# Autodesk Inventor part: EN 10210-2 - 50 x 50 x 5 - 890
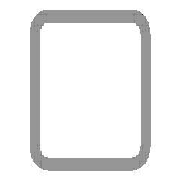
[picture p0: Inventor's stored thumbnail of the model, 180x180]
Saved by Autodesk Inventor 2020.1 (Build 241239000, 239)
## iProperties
_CCFamilyMember: 16
_CCFamilyDisplayName: DIN EN 10210-2 (USAS B17.1 quadratisch) - Rohrleitung — In Klammern angegebene Größen wurden aufgehoben
_FrameMemberDoc: Frame Member File
_Version: 15.0.0
_GetPNFromCC: 1
IsCustomPart: 1
Created: 2019-10
Part Number: EN 10210-2 - 50 x 50 x 5 - 890
Material: Stahl, weich
Description: Rohrleitung
Document SubType Name: Modeling
Standard: DIN
Designer: lutzd
Standard Revision: 2006-07
Standards Organization: DIN
Language: de-DE
Size Designation: 50 x 50 x 5
Categories: <MemberInstance><Categories><Category DisplayName="Profile" InternalName="089c4875-fa83-4c05-b084-43b9cc11f5ed" Mnemonic="GRDR"><CategoryParameter DisplayName="
Stock Number: 50 x 50 x 5
Mass: 6096.35 g
Surface Area: 3031.52 cm^2
Volume: 776.605 cm^3
Density: 7.85 g/cm^3
Appearance: Halbpoliert
G_L: 890,000 mm
G_W: 50,000 mm
G_H: 50,000 mm
Dimensions: 50x50x890 mm
Mass: 6,096 kg
DocNumber: ADSK-014096
Folder: .
+62D9DE20-FE77-4E76-B15A-D3B66BCC2A71+SCHNITTDETAIL1: Schnittwinkel 90,00 grd
+BCCFB225-26FE-409D-8E77-CCDF25C108BC+SCHNITTDETAIL2: Schnittwinkel 90,00 grd
Title: Profil-Bauteil
Author: lutzd
Revision Number: -
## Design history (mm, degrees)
node "Startebene"
node "Endebene"
sketch "Skizze"
  geometry: L1 (-25, -17.5)-(-25, 17.5); L2 (-17.5, 25)-(17.5, 25); L3 (25, 17.5)-(25, -17.5); L4 (17.5, -25)-(-17.5, -25); L5 (-15, 20)-(15, 20); L6 (20, 15)-(20, -15); L7 (15, -20)-(-15, -20); L8 (-20, -15)-(-20, 15); L9 (0, 37.175)-(0, -37.175) reference; L10 (-37.175, 0)-(37.175, 0) reference; A1 r 7.5 centre (-17.5, -17.5) between (-25, -17.5) and (-17.5, -25); A2 r 7.5 centre (-17.5, 17.5) between (-17.5, 25) and (-25, 17.5); A3 r 7.5 centre (17.5, 17.5) between (25, 17.5) and (17.5, 25); A4 r 7.5 centre (17.5, -17.5) between (17.5, -25) and (25, -17.5); A5 r 5 centre (-15, -15) between (-20, -15) and (-15, -20); A6 r 5 centre (-15, 15) between (-15, 20) and (-20, 15); A7 r 5 centre (15, 15) between (20, 15) and (15, 20); A8 r 5 centre (15, -15) between (15, -20) and (20, -15)
  constraints: 16 end point, 16 point on circle, 16 tangent, 8 centre point, 6 equal radius, 4 parallel, 2 perpendicular, 2 other
  dimensions: "d7" = 7.5 radius of A1 (= G_IR); "d10" = 50 distance between parallel lines of L2 L4 (= G_H); "d11" = 50 distance between parallel lines of L1 L3 (= G_W); "d12" = 5 distance between parallel lines of L3 L6 (= G_T); "d15" = 25 distance between parallel lines of L2 L10 (= 0.5 x d10); "d16" = 25 distance between parallel lines of L9 L3 (= 0.5 x d11); "d19" = 5 radius of A5 (= G_T); "d20" = 5 distance between parallel lines of L4 L7 (= G_T)
extrude "Körper" new body sketch "Skizze" stored distance "d3" = 890 (= G_L); taper "d4" = 0 deg
node "Driven Length"
  sketch "Sketch3"
    geometry: L1 (0, 0)-(10, 0) reference
    constraints: 2 end point, 1 horizontal
  workplane "Work Plane3"
  sketch "Sketch4"
    geometry: L1 (-2, 50)-(12, 50) reference; L2 (-2, 940)-(12, 940) reference
    dimensions: "d18" = 890 distance between parallel lines of L1 L2 (derived)
workplane "Arbeitsebene4"
feature "Trennen1"
workplane "Arbeitsebene5"
feature "Trennen2"
sketch "Skizze5"
  geometry: L1 (890, -35)-(890, 0) reference; L2 (890, -17.5)-(600, -17.5); 4 further points
  constraints: 2 end point, 2 point on line, 1 coincident, 1 horizontal, 1 midpoint
  dimensions: "d21" = 115 distance of point (715, -17.5) point (600, -17.5); "d22" = 115 distance of point (830, -17.5) point (715, -17.5) (= d21); "d23" = 60 distance from line of L1 point (830, -17.5)
hole "Bohrung1" sketch "Skizze5" at (600, -17.5), (715, -17.5), (830, -17.5) diameter "d24" = 6.647; stored, may be unused: countersink angle "d28" = 90 deg, drill point angle "d30" = 118 deg; dims "d25" = 16, "d26" = 4, "d27" = 2, "d29" = 22.2
body "Solid1"
other parameters: "G_W" = 50 [user parameter; used in 1 equation term], "G_H" = 50 [user parameter; used in 1 equation term], "G_T" = 5 [user parameter; used in 3 equation terms], "G_IR" = 7.5 [user parameter; used in 1 equation term], "G_L" = 890 (= d18) [user parameter; used in 1 equation term], "d17" = 90 deg
